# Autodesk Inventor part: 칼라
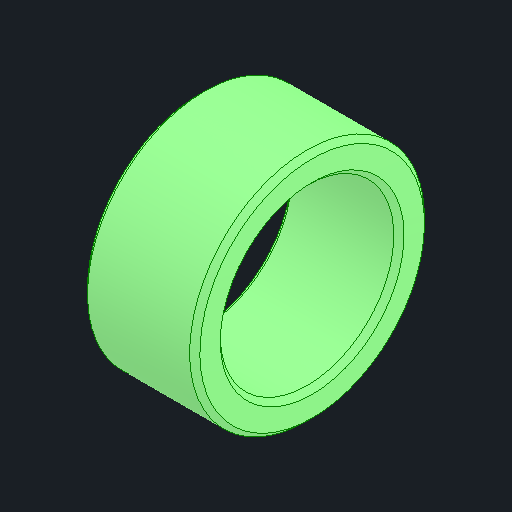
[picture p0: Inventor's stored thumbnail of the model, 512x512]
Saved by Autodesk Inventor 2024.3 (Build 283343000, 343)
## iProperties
Created: 2025-03
Part Number: 칼라
Material: 일반
Document SubType Name: Modeling
Designer: user
Density: 1 g/cm^3
Appearance: 기본값
Author: jhkim
Sending System: Autodesk Inventor 2025
Preprocessor: ST-DEVELOPER v20
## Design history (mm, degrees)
feature "솔리드1"
node "솔리드2"
